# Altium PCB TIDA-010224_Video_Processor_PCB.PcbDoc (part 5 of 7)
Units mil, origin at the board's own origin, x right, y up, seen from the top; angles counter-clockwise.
Board outline 2355.46 x 4164 mil, 10 copper layers (L1-Top Layer, L2-GND, L3-SIG1, L4-GND, L5-PWR, L6-PWR, L7-GND, L8-SIG2, L9-GND, L10-Bottom Layer), stack 62.2 mil thick; 508 components, 274 nets, 3619 pads, 705 vias.
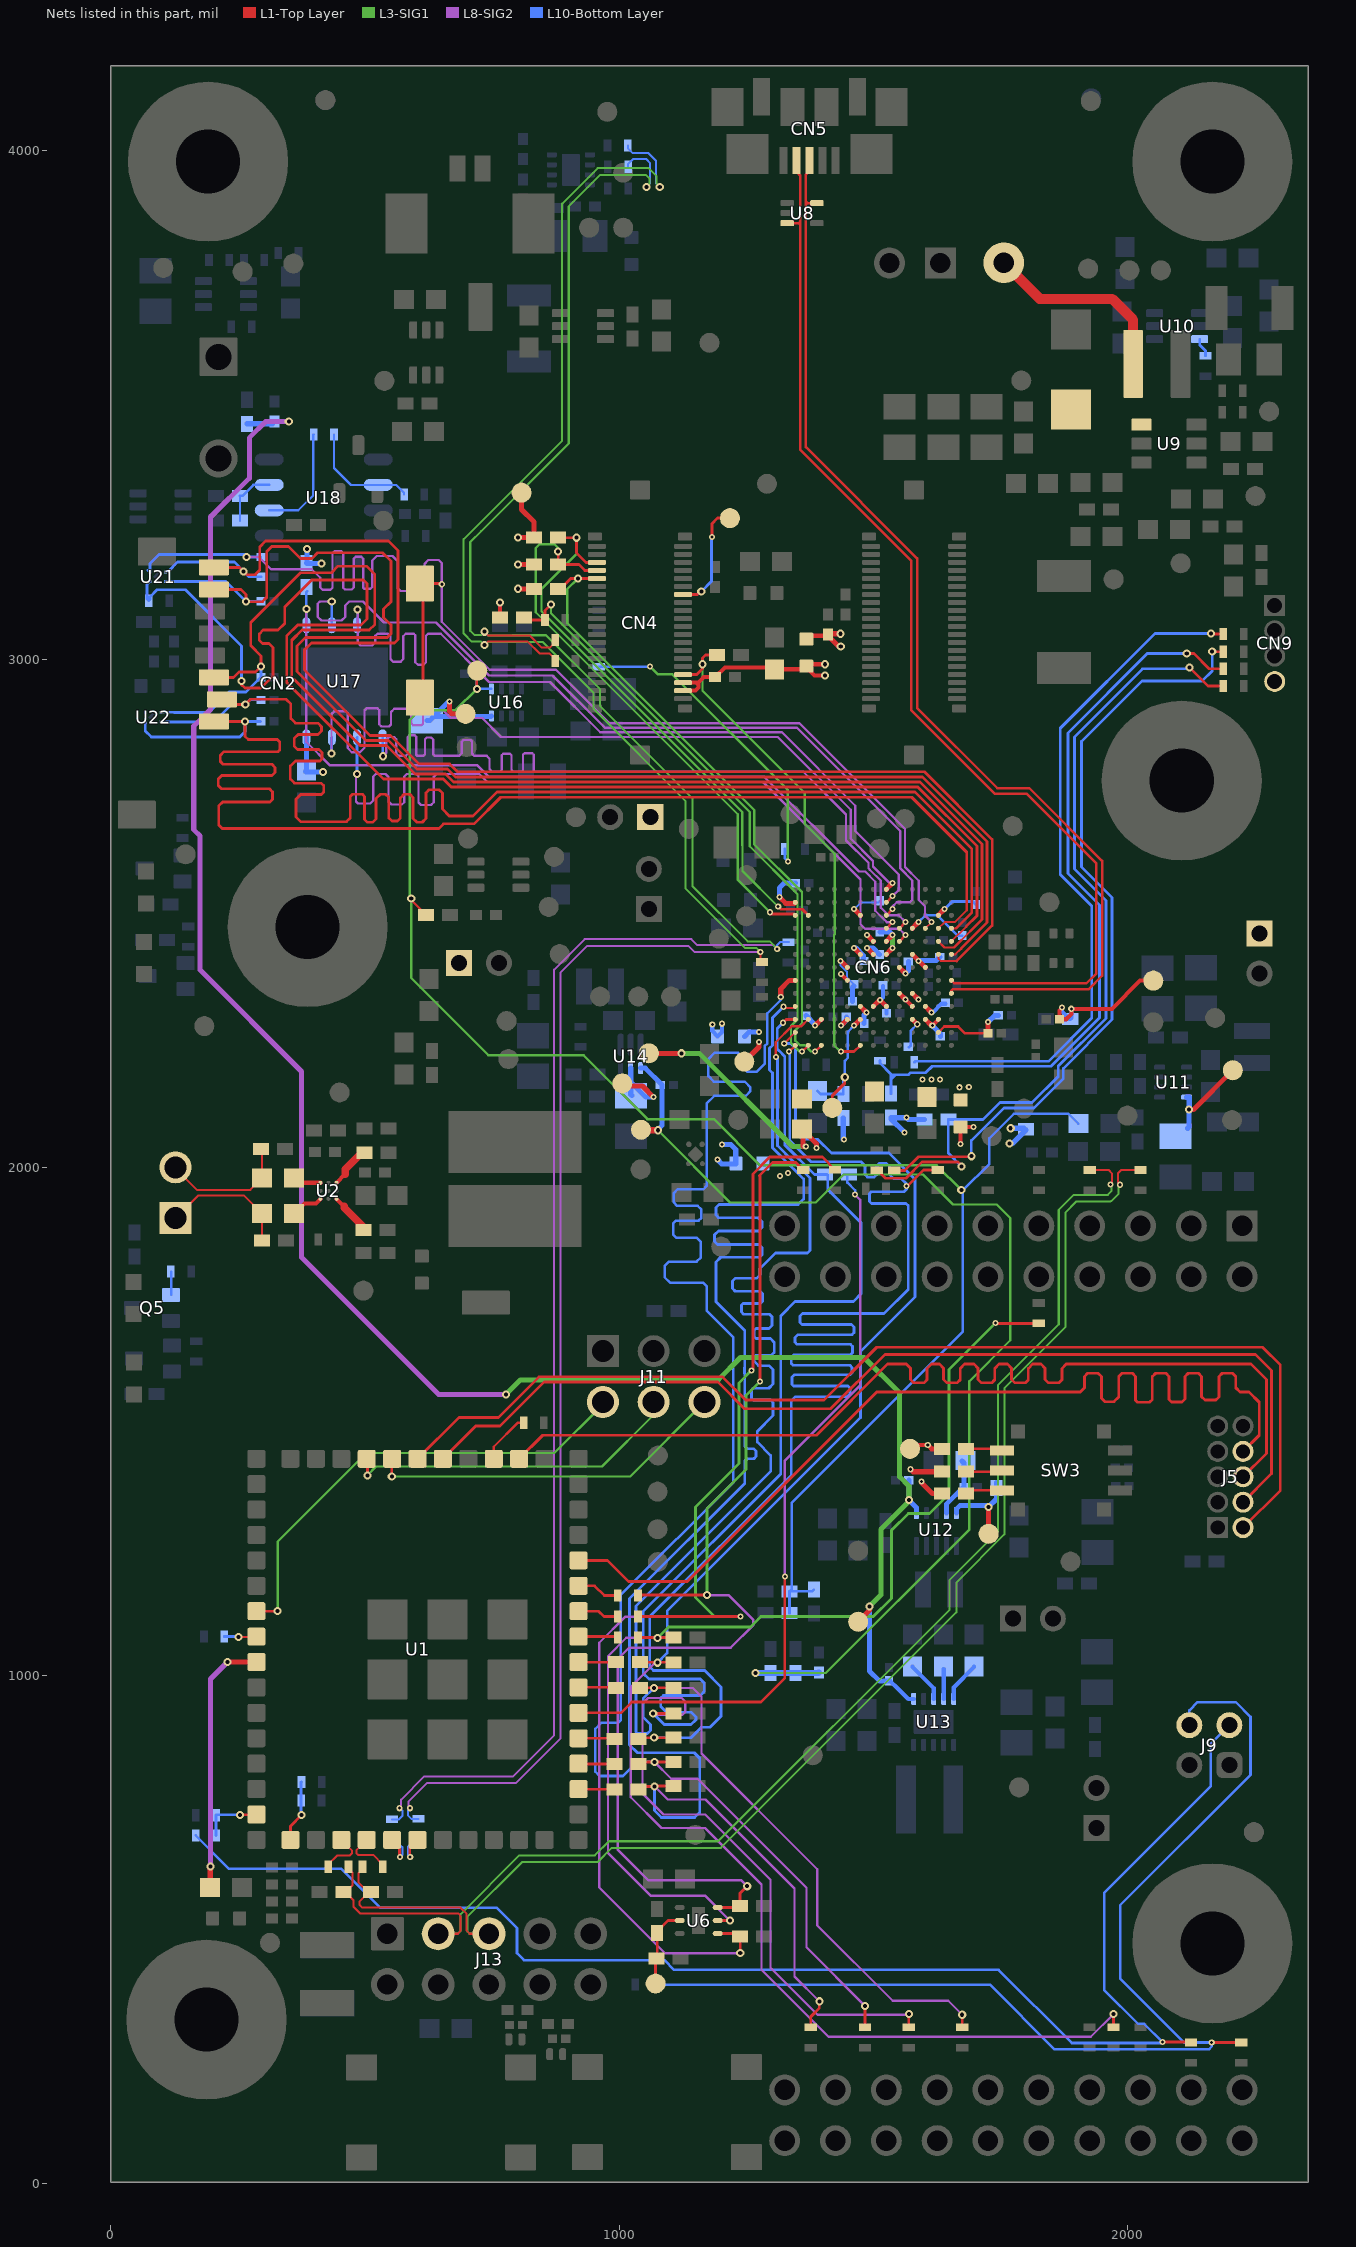
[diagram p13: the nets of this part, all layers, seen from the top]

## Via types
v1: diameter 16, hole 8, L1-Top Layer to L10-Bottom Layer, tented both sides, 414 vias
v2: diameter 12, hole 6, L1-Top Layer to L10-Bottom Layer, tented both sides, 243 vias
v3: diameter 19.68, hole 7.87, L1-Top Layer to L10-Bottom Layer, 44 vias
v4: diameter 14, hole 6, L1-Top Layer to L10-Bottom Layer, tented both sides, 2 vias
v5: diameter 16, hole 8, L1-Top Layer to L10-Bottom Layer, tented top, 1 vias
v6: diameter 20, hole 10, L1-Top Layer to L10-Bottom Layer, tented both sides, 1 vias

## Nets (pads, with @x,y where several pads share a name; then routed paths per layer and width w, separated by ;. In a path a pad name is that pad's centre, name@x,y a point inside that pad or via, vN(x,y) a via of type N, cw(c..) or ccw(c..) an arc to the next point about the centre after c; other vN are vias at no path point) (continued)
NetQ5_1: Q5.1 R180.2 | length 46.3
  L10-Bottom Layer w4.5: R180.2@118,1795 118.4,1794.6 Q5.1@118.4,1748.89
NetR1_2: R1.2 U1.36 | length 514.8
  L1-Top Layer w10: R1.2@195.35,582.95 195.35,623.64 v1(196,624.29) ; v1(229.33,1026.67) U1.36@286.33,1026.67
  L8-SIG2 w10: v1(196,624.29) 196,993.33 v1(229.33,1026.67)
NetR2_1: R2.1 U2.C3 | length 58.9
  L1-Top Layer w8: R2.1@360.5,1979 360.5,1981.28 372.1,1969.68 U2.C3@412.32,1969.68
NetR3_1: R3.1 U2.A3 | length 63.9
  L1-Top Layer w8: R3.1@360.5,1909 380.5,1929 403.14,1929 U2.A3@412.32,1938.18
NetR8_1: R8.1 U1.46 | length 95.5
  L1-Top Layer w4: R8.1@427.48,623.74 427.48,628.45 445.03,646 470.1,646 474,649.9 474,655.96 U1.46@453.26,676.7
NetR9_2: R9.2 U2.A1 | length 83.4
  L1-Top Layer w8: U2.A1@443.82,1938.18 459,1923
  L1-Top Layer w15: 459,1923 459,1920.9 497.38,1882.53 R9.2@497.38,1877
NetR10_2: R10.2 U2.C1 | length 82.8
  L1-Top Layer w8: U2.C1@443.82,1969.68 461,1986.86
  L1-Top Layer w15: 461,1986.86 461,1996.28 489.63,2024.91 R10.2@498.26,2024.91
NetR12_1: R12.1 U1.47 | length 100.3
  L1-Top Layer w4: U1.47@503.26,676.7 482.92,656.36 482.92,650.38 486.12,647.17 515.74,647.17 534.89,628.03 R12.1@534.89,623.74
NetR17_1: R17.1 U1.19 | length 102
  L1-Top Layer w5: U1.19@753.26,1426.63 753.26,1450.26 800.61,1497.61 R17.1@812,1497.61
NetR25_1: R25.1 U1.4 | length 74.1
  L1-Top Layer w5: U1.4@920.19,826.67 920.85,826 R25.1@990.38,826 R25.1@994,826
NetR26_1: R26.1 U1.3 | length 74.1
  L1-Top Layer w5: U1.3@920.19,776.67 993.33,776.67 R26.1@994,776
NetR27_1: R27.1 U1.8 | length 76.9
  L1-Top Layer w5: U1.8@920.19,1026.67 996.67,1026.67 R27.1@997,1026.34
NetR28_1: R28.1 U1.7 | length 77.1
  L1-Top Layer w5: U1.7@920.19,976.67 996.2,976.67 R28.1@997,975.87
NetR29_1: R29.1 U1.5 | length 77.5
  L1-Top Layer w5: U1.5@920.19,876.67 995.27,876.67 R29.1@997,874.93
NetR30_1: R30.1 U1.11 | length 83.1
  L1-Top Layer w5: U1.11@920.19,1176.67 951.79,1176.67 970.9,1157.56 R30.1@995.35,1157.56
NetR31_1: R31.1 U1.10 | length 81.2
  L1-Top Layer w5.5: U1.10@920.19,1126.67 959.33,1126.67 970,1116 R31.1@997,1116
NetR32_1: R32.1 U1.9 | length 77.5
  L1-Top Layer w5.5: U1.9@920.19,1076.67 995.33,1076.67 R32.1@997,1075
NetR55_1: R55.1 SW3.1 | length 72
  L1-Top Layer w5: R55.1@1682.73,1446.12 1750.69,1446.12 SW3.1@1753.55,1443.26
NetR56_1: R56.1 SW3.3 | length 73.5
  L1-Top Layer w5.5: R56.1@1682.73,1358.12 1689.13,1364.52 SW3.3@1753.55,1364.52
NetR57_1: R57.1 SW3.2 | length 71.8
  L1-Top Layer w5: R57.1@1682.92,1401.12 1750.77,1401.12 SW3.2@1753.55,1403.89
NetR90_2: R90.2 U10.3 | length 37.4
  L10-Bottom Layer w5.5: U10.3@2142.29,3629.58 2142.29,3618.63 2154,3606.92 R90.2@2154,3597
NetR108_2: R108.2 U13.5 | length 80.2
  L10-Bottom Layer w8: U13.5@1658.37,954.15 1658.37,976.87 1698.66,1017.16 R108.2@1698.66,1017.63
NetR109_1: R109.1 R110.2 U12.4 | length 118.9
  L10-Bottom Layer w10: U12.4@1643.86,1319.65 1643.86,1337.04 1677.57,1370.75 R109.1@1678.53,1370.75 1678.53,1418.15 R110.2@1674.69,1422
NetR112_2: R112.2 U13.4 | length 59.3
  L10-Bottom Layer w8: R112.2@1638.37,1013.34 1638.68,1013.03 U13.4@1638.68,954.15
NetR114_2: R114.2 U13.3 | length 80.7
  L10-Bottom Layer w8: R114.2@1577.54,1017.63 1577.54,1017.13 1619,975.67 U13.3@1619,954.15
NetR121_1: R121.1 U1.6 | length 1499.7
  L1-Top Layer w5: U1.6@920.19,926.67 1003.67,926.67 1025,948 1279,948 1326,995 v2(1326,1195)
  L8-SIG2 w5: v2(1326,1195) 1326,1422.9 1474,1570.9 1474,1936.29 v2@1461.5,1948.79
  L10-Bottom Layer w5: R121.1@1449.13,1986 1449.13,1970.24 1464.42,1954.95 v2(1464.42,1947)
NetR154_1: R154.1 R158.2 U18.6 | length 227.3
  L10-Bottom Layer w4.5: R158.2@439,3442 439.03,3376.18 472.32,3342.89 U18.6@526.01,3342.89 561.53,3342.89 576.81,3327.6 R154.1@576.81,3324.01
NetR155_1: R155.1 U1.49 | length 87.8
  L1-Top Layer w5.5: v2@587.86,642.63 587.86,661.3 U1.49@603.26,676.7
  L10-Bottom Layer w4: v2(588.86,643) 584.75,647.11 584.75,663.87 595.69,674.82 R155.1@605,674.82
NetR156_1: R156.1 U1.48 | length 86.5
  L1-Top Layer w5.5: U1.48@553.26,676.7 568,661.96 v2@568,643.2
  L10-Bottom Layer w4: R156.1@553,675.54 560.11,675.54 573.25,662.41 573.25,647.25 v2(569,643)
NetR158_1: R158.1 U18.2 | length 218.8
  L10-Bottom Layer w4.5: U18.2@311.44,3292.89 368.49,3292.89 398.32,3322.72 398.32,3441.32 R158.1@399,3442
NetR159_1: R159.1 R160.1 U1.44 | length 123.6
  L1-Top Layer w5.5: U1.44@353.26,676.7 353.26,703.5 v1(375.09,725.33)
  L10-Bottom Layer w5.5: R159.1@374.86,790.65 374.22,790.01 R160.1@374.22,754 374.22,727.74 375.09,726.87 v1(375.09,725.33)
NetR172_2: R172.2 R173.2 U18.3 | length 115.5
  L10-Bottom Layer w4.5: R173.2@253.81,3272.35 R172.2@253.81,3321.35
  L10-Bottom Layer w5: R172.2@253.81,3321.35 258.55,3321.35 280.09,3342.89 U18.3@311.44,3342.89
NetR175_2: R175.2 U1.35 | length 63.6
  L1-Top Layer w4: v1(251.28,1076.2) 285.87,1076.2 U1.35@286.33,1076.67
  L10-Bottom Layer w5.5: R175.2@223.09,1076.67 250.81,1076.67 v1(251.28,1076.2)
NetR176_1: R176.1 R177.1 U1.42 | length 119.9
  L1-Top Layer w5.5: v1(254.22,726) 285.67,726 U1.42@286.33,726.67
  L10-Bottom Layer w5.5: R177.1@206.92,685.43 R176.1@206.92,725.33 207.59,726 v1(254.22,726)
OPT_ADDR: ID.1 R33.2 R34.1 U6.2 | length 157.3
  L1-Top Layer w5.5: ID.1@1071.7,394.05 1071.7,441.73 R33.2@1073.33,443.36 1074.95,444.98 R34.1@1074.95,493.82 1074.95,496.95 1096.15,518.15 U6.2@1119.17,518.15
OPT_INT: R32.2 R65.2 R187.1 U6.5 | length 2117.9
  L1-Top Layer w5.5: R32.2@1037,1075 R187.1@1107.38,1075 R187.1@1107.48,1075 ; U6.5@1193.97,518.15 v1(1217.78,518.15) ; v2(1740.75,1693.79) 1744.54,1693.79 1745.33,1693 R65.2@1825.78,1693
  L3-SIG1 w5.5: v1(1075.48,1074.27) 1096.98,1095.77 1258.55,1095.77 1278.78,1116 1500,1116 1536,1152 1536,1285.98 1569.02,1319 1610.53,1319 1649.01,1357.48 1649.01,1602.05 v2(1740.75,1693.79)
  L8-SIG2 w4.5: v1(1075.48,1074.27) 1014.05,1074.27 978,1038.22 978,650.64 1061.64,567 1168.93,567 v1(1217.78,518.15)
OPT_SCL: R31.2 R44.2 R49.1 U6.4 | length 2563.7
  L1-Top Layer w5.5: R31.2@1037,1116 v2(1239,1116) ; U6.4@1193.97,492.56 1232.31,492.56 R44.2@1238.22,486.65 v1(1238.22,453.81) ; v2(1260.44,1600.68) 1263.16,1603.4 1263.16,1987.07 1296.32,2020.23 1399.77,2020.23 R49.1@1425,1995
  L3-SIG1 w5.5: v2(1239,1116) 1187.84,1116 1150.2,1153.64 1150.2,1331.93 1235.73,1417.47 1235.73,1575.97 v2(1260.44,1600.68)
  L8-SIG2 w4.5: v1(1238.22,453.81) 1090.19,453.81 961,583 961,1064.39 1012.61,1116 v2(1239,1116)
OPT_SDA: R30.2 R43.2 R47.1 U6.6 | length 2272.2
  L1-Top Layer w5.5: R30.2@1038.63,1158.33 v1(1173,1158.33) ; U6.6@1193.97,543.74 1235.59,543.74 R43.2@1238,546.15 1238,571.59 v1(1251.97,585.56) ; v2(1277,1579) 1277,1982.68 1276,1983.68 1302,2009.68 1347.57,2009.68 R47.1@1362.42,1994.84
  L3-SIG1 w5.5: v1(1173,1158.33) 1173,1329 1249.41,1405.41 1249.41,1551.41 v2(1277,1579)
  L8-SIG2 w4.5: v1(1173,1158.33) 1215.23,1158.33 1264.13,1109.43 1264.13,1099.49 1219.65,1055 1020,1055 997,1032 997,658 1058,597 1240.53,597 v1(1251.97,585.56)
OV_RST#: C102.1 CN6.C8 R122.1 RST.1 | length 281.9
  L1-Top Layer w5.5: RST.1@1419.35,2117 1419.35,2140.88 1444,2165.54 v1(1444,2177.37)
  L1-Top Layer w10: v2(1462.36,2279) CN6.C8@1474.59,2291.23
  L10-Bottom Layer w5: 1444,2209.47 1449.86,2215.33 1449.86,2266.5 v2(1462.36,2279)
  L10-Bottom Layer w5.5: C102.1@1390.52,2150.06 1396.13,2144.45 R122.1@1441,2144.45 v1@1441,2176.46 ; v1(1444,2177.37) 1444,2209.47
OV_RXD0: R52.2 R83.2 R111.1 | length 1638.2
  L1-Top Layer w5.5: R52.2@1507,1994 1508.83,1994 1524.36,1978.47 1564.23,1978.47 1596.05,2010.29 1667,2010.29 v1@1672,2005.29 ; v1(2122.13,2983.54) 2158.7,2946.98 R83.2@2188.81,2946.98
  L10-Bottom Layer w5.5: v1(1673.76,2001.79) 1647.62,2027.92 R111.1@1647.62,2094 1716.22,2094 1749.76,2127.54 1812.4,2127.54 1864,2179.14 1864,2199.24 1957.78,2293.02 1957.78,2525.22 1896,2587 1896,2847 2029.98,2980.98 2119.57,2980.98 v1(2122.13,2983.54)
OV_RXD1: R82.2 R117.1 R119.2 | length 1513.1
  L1-Top Layer w5.5: v1(2116.82,3011.12) 2130.92,3011.12 2161.06,2980.98 R82.2@2188.81,2980.98
  L10-Bottom Layer w5.5: R119.2@1513,2210 1513,2205.22 1535,2183.22 ; R117.1@1535,2144.92 1535,2173.25 ; v1(2116.82,3011.12) 2039.12,3011.12 1882.93,2854.93 1882.93,2589.79 1883,2589.72 1883,2578.01 1945,2516.01 1945,2294.4 1849.6,2199 1616,2199 1603.32,2186.32 1573.46,2186.32 1569.38,2182.25 1544,2182.25 ; 1535,2173.25 1544,2182.25 ; 1535,2173.25 1535,2183.22 ; 1535,2183.22 1535.97,2182.25 1544,2182.25
OV_TXD0: R53.2 R81.2 | length 1536.1
  L1-Top Layer w5.5: R53.2@1541.34,1994 1561.82,1994 1588.82,2021 v1@1692,2021 ; v1(2166.96,3015) 2162.53,3015 2162.17,3014.64 R81.2@2188.81,3014.64
  L10-Bottom Layer w5.5: v1(1693,2022) 1693,2052.7 1757.3,2117 1816,2117 1874,2175 1874,2194.72 1970,2290.72 1970,2531 1910,2591 1910,2838.33 2028.67,2957 2146.93,2957 2166.96,2977.03 v1(2166.96,3015)
OV_TXD1: R80.2 R115.2 | length 1379.6
  L1-Top Layer w5.5: v1(2164.68,3050.75) 2165.7,3049.72 R80.2@2188.81,3049.72
  L10-Bottom Layer w5.5: R115.2@1581,2207 1583,2209 1845.46,2209 1930,2293.54 1930,2514.5 1868,2576.5 1868,2864 2054.75,3050.75 v1(2164.68,3050.75)
P16_JTAG_TDI: J5.8 U1.12 | length 2071.4
  L1-Top Layer w5.5: U1.12@920.19,1226.67 976.84,1226.67 1018.5,1185 1134,1185 1166,1217 1506.83,1557.83 1907.33,1557.83 1915.84,1566.34 1915.84,1588.78 1921.89,1594.83 1942.2,1594.83 1948.83,1588.2 1948.83,1545.71 1955.54,1539 1973.68,1539 1983.17,1548.49 1983.17,1588.2 1989.8,1594.83 2010.11,1594.83 2016.16,1588.78 2016.16,1541.84 2020.27,1537.73 2043.73,1537.73 2049.17,1543.17 2049.17,1588.2 2055.8,1594.83 2076.11,1594.83 2082.16,1588.78 2082.16,1543.37 2086.99,1538.54 2107.57,1538.54 2113.17,1544.14 2113.17,1588.2 2119.8,1594.83 2140.11,1594.83 2146.16,1588.78 2146.16,1548.6 2152.76,1542 2173.81,1542 2180.17,1548.36 2180.17,1588.2 2186.8,1594.83 2207.11,1594.83 2213.16,1588.78 2213.16,1566.34 2221.67,1557.83 2239.45,1557.83 2259.55,1537.73 2259.55,1472.98 J5.8@2227.7,1441.13
P17_JTAG_TDO: J5.6 U1.18 | length 2054.9
  L1-Top Layer w5.5: U1.18@803.26,1426.63 849.63,1473 1388.34,1473 1528.34,1613 1564.84,1613 1573.01,1604.83 1573.01,1582.63 1579.64,1576 1599.95,1576 1606,1582.05 1606,1604.49 1614.51,1613 1630,1613 1638.17,1604.83 1638.17,1582.63 1644.8,1576 1665.11,1576 1671.16,1582.05 1671.16,1604.49 1679.67,1613 1698,1613 1706.17,1604.83 1706.17,1582.63 1712.8,1576 1733.11,1576 1739.16,1582.05 1739.16,1604.49 1747.67,1613 1764,1613 1772.17,1604.83 1772.17,1582.63 1778.8,1576 1799.11,1576 1805.16,1582.05 1805.16,1604.49 1813.67,1613 1830,1613 1838.17,1604.83 1838.17,1582.63 1844.8,1576 1865.11,1576 1871.16,1582.05 1871.16,1604.49 1879.67,1613 2243.28,1613 2273.87,1582.41 2273.87,1437.3 J5.6@2227.7,1391.13
P19_JTAG_TCK: J5.4 U1.21 | length 2054.8
  L1-Top Layer w5.5: U1.21@653.26,1426.63 717.77,1491.13 765.2,1491.13 851.87,1577.8 1194.2,1577.8 1247,1525 1416,1525 1523,1632 2251.87,1632 2283.87,1600 2283.87,1397.3 J5.4@2227.7,1341.13
P20_JTAG_TMS: J5.2 U1.22 | length 2191.3
  L1-Top Layer w5.5: U1.22@603.26,1426.63 684.63,1508 762.42,1508 842.21,1587.8 1203.33,1587.8 1249.13,1542 1402.89,1542 1506.89,1646 2266,1646 2301,1611 2301,1364.43 J5.2@2227.7,1291.13
PG_1V1: PG_1.1V.1 R137.1 U14.2 | length 185.2
  L1-Top Layer w10: PG_1.1V.1@1006.23,2165.13 1011.27,2160.09 1045.89,2160.09 v2(1067.79,2138.19)
  L10-Bottom Layer w10: U14.2@1022.79,2195.21 1022.79,2167.96 ; R137.1@1025,2141 1022.79,2143.21 1022.79,2167.96 ; v2(1067.79,2138.19) 1052.57,2138.19 1022.79,2167.96
PG_1V8: PG_1.8V.1 R152.1 U16.8 | length 226.1
  L1-Top Layer w10: v2(666,2916.5) 666,2897.57 671.25,2892.32 PG_1.8V.1@697.73,2892.32
  L10-Bottom Layer w10: R152.1@622,2879 627.44,2879 R152.1@635.44,2887 ; v2(666,2916.5) 664.94,2916.5 R152.1@635.44,2887 ; U16.8@748.67,2888.2 747.47,2887 R152.1@635.44,2887
PG_1V35: PG_1.35V.1 R91.1 U11.8 | length 180.3
  L1-Top Layer w10: v1(2121.03,2114) 2130.44,2114 PG_1.35V.1@2207.53,2191.09
  L10-Bottom Layer w10: U11.8@2116.83,2137.98 2121.8,2137.98 v1@2121.8,2118.97 ; R91.1@2118.8,2077.03 2121.03,2079.27 v1(2121.03,2114)
PG_3V3A: PG_3.3V.1 R107.1 U12.5 | length 182.7
  L1-Top Layer w10: PG_3.3V.1@1727,1279 v1(1727,1332)
  L10-Bottom Layer w10: U12.5@1663.54,1319.65 1663.54,1327.4 1671.14,1335 1724,1335 v1(1727,1332) 1742.54,1347.54 R107.1@1742.54,1369.06 R107.1@1742.54,1379.69
PIR_OUT1: J9.4 R84.1 R136.2 | length 2237.1
  L1-Top Layer w5: v2(2166,278) R84.1@2224.03,278
  L10-Bottom Layer w5: R136.2@1071.7,392 1729.48,392 1856.85,264.63 2160.24,264.63 2166,270.38 v2(2166,278) 2111.42,278 1985.7,403.72 1985.7,548.07 2242.29,804.66 2242.29,918.82 2213.25,947.87 2138.38,947.87 2121.91,931.4 J9.4@2121.91,902.37
PIR_OUT2: J9.2 R75.1 R177.2 | length 2937.9
  L1-Top Layer w5: v2(2068.76,279) 2122.1,279 2123.05,279.95 R75.1@2125,278
  L10-Bottom Layer w5: R177.2@166.92,685.43 232.57,619.78 453.26,619.78 529.54,543.5 758.5,543.5 799,503 799,453.71 812.71,440 1089,440 1108,421 1746.8,421 1890.8,277 2066.76,277 v2(2068.76,279) 2032.82,314.94 2021,314.94 1954.32,381.62 1954.32,572.23 2164,781.91 2164,865.72 J9.2@2200.65,902.37
PWR_EN: C130.2 PWR_EN.1 R116.1 R118.1 R170.1 U12.1 U13.1 | length 4076
  L1-Top Layer w10: PWR_EN.1@1470.37,1105.91 1492.84,1128.38 v1(1492.84,1136.22)
  L3-SIG1 w10: v1(777,1553) 806,1582 1195,1582 1239,1626 1482,1626 1552,1556 1552,1391 1570,1373 v1(1570,1345.36) 1570,1342.56 1515,1287.57 1515,1158.38 v1(1492.84,1136.22)
  L8-SIG2 w10: v1(350,3467.63) 304.49,3467.63 272.39,3435.53 272.39,3356.01 196,3279.61 196,2901 163,2868 163,2664.57 175.5,2652.07 175.5,2388.31 375,2188.81 375,1822.98 644.98,1553 v1(777,1553)
  L10-Bottom Layer w8: R118.1@1533.35,989.63 1547.92,975.07 1568.84,954.15 U13.1@1579.63,954.15
  L10-Bottom Layer w10: R170.1@267.38,3463.19 317.56,3463.19 C130.2@322,3467.63 v1(350,3467.63) ; v1(1492.84,1136.22) 1492.84,1008.73 1511.94,989.63 R118.1@1533.35,989.63 ; R116.1@1570,1384.69 v1(1570,1345.36) 1584.8,1330.56 U12.1@1584.8,1319.65
RDY: CN6.F13 R25.2 R39.2 R50.2 | length 3300.1
  L1-Top Layer w5.5: R25.2@1034,826 1038,830 v1(1069.58,830) R39.2@1107.38,830 ; R50.2@1483.78,311.81 1484,312.03 v1(1484,350)
  L1-Top Layer w10: v2(1318,2335) 1318,2351.09 1334.91,2368 CN6.F13@1346.64,2368
  L8-SIG2 w4.5: v1(1069.58,830) 1102.58,797 1154,797 1368.56,582.44 1368.56,465.44 v1(1484,350)
  L10-Bottom Layer w5: v1(1069.58,830) 1034.78,830 1007.21,802.43 961.57,802.43 953,811 953,894.95 965.4,907.34 998.31,907.34 1002.96,912 1002.96,1158.33 1224.69,1380.06 1224.69,1665.53 1172.25,1717.97 1172.25,1766.27 1165.77,1772.75 1100.68,1772.75 1089.61,1783.82 1089.61,1805.61 1098.37,1814.36 1152.31,1814.36 1160.86,1822.91 1160.86,1853.45 1152.96,1861.35 1113.17,1861.35 1106.31,1868.2 1106.31,1889.15 1112.28,1895.12 1156.39,1895.12 1161.68,1900.4 1161.68,1917.43 1154.69,1924.41 1114.15,1924.41 1107.51,1931.06 1107.51,1949.45 1115,1956.95 1165.59,1956.95 1172.25,1963.6 1172.25,2125.7 1187.47,2140.92 1249.41,2140.92 1258.41,2149.92 1258.41,2157.29 1247.23,2168.47 1186.47,2168.47 1175.46,2179.49 1175.46,2213.12 1187.84,2225.5 1234.22,2225.5 1240.16,2219.56 1240.16,2200.09 1251.79,2188.46 1270.88,2188.46 1286.16,2203.74 1286.16,2238.53 1291.77,2244.15 1291.77,2303.29 1318,2329.52 v2(1318,2335)
SC_CD: CN2.10 CN6.K3 R167.1 U21.4 | length 2797.2
  L1-Top Layer w4: CN6.K3@1602.54,2470.36 v2(1614.77,2482.59)
  L1-Top Layer w5.5: CN2.10@608.03,2924.29 614.01,2930.26 614.01,3124.66 608.03,3130.64 CN2.10@608.03,3148.7 649.71,3148.7 v2(651,3147.41)
  L8-SIG2 w4.5: v1(267,3201) 291,3201 315,3177 395,3177 412,3160 412,3141.2 416.51,3136.69 432.01,3136.69 436,3140.68 436,3208 441,3213 452.58,3213 457.22,3208.36 457.22,3140.29 460.51,3137 473.8,3137 478,3141.2 478,3198 481.51,3201.51 492.49,3201.51 496.3,3197.7 496.3,3140.7 498.49,3138.51 510.51,3138.51 514,3142 514,3194 523,3203 554,3203 564,3193 564,3140 570,3134 613.31,3134 616.81,3137.51 616.81,3187.41 624.4,3195 645,3195 651,3189 v2(651,3147.41) 651,3073.54 745.22,2979.31 875.85,2979.31 981.16,2874 1354.83,2874 1562.39,2666.44 1562.39,2591.12 1589.54,2563.97 1589.54,2526.34 1601.93,2513.96 1601.93,2495.43 v2(1614.77,2482.59)
  L10-Bottom Layer w5.5: 73.1,3175 U21.4@76.65,3171.45 76.65,3188.08 94.36,3205.8 262.2,3205.8 v1(267,3201) R167.1@294.36,3201
SC_CLK: CN6.J1 R184.2 U21.3 | length 2842.4
  L1-Top Layer w4: CN6.J1@1653.72,2444.77 1682.81,2473.86
  L1-Top Layer w5.5: v1(257,2957.18) 257,2949.63 263.65,2942.98 295.44,2942.98 319,2966.54 319,3023 311,3031 298,3031 292,3037 292,3049.72 299.4,3057.12 328.81,3057.12 342,3070.31 342,3102.98 395.02,3156 496.76,3156 504,3148.76 504,3078.91 492.21,3067.12 367.56,3067.12 345.77,3045.33 345.77,2954.57 536.34,2764 654,2764 669.64,2748.36 1587.62,2748.36 1704,2631.99 1704,2495.05 1682.81,2473.86
  L10-Bottom Layer w5.5: R184.2@74.52,3115 71,3118.52 71,3146.91 U21.3@76.65,3152.55 ; R184.2@76.65,3117.12 76.65,3122.63 90.52,3136.5 146.5,3136.5 257,3026 v1(257,2957.18)
SC_CMD: CN2.3 CN6.J2 R164.1 U22.1 | length 2843.5
  L1-Top Layer w4: CN6.J2@1628.13,2444.77 1640.25,2432.65 1658.85,2432.65 1691,2464.8
  L1-Top Layer w5.5: CN2.3@202.52,2964.05 240.8,2964.05 251.75,2975 284.31,2975 v1(295.02,2985.71) 295.02,3006.5 275,3026.52 275,3072.35 372.65,3170 434,3170 447,3183 502.71,3183 519.27,3166.44 519.27,3068.27 508.12,3057.12 375.79,3057.12 355.77,3037.11 355.77,2964.82 490.59,2830 542.06,2830 598.06,2774 658.14,2774 673.78,2758.36 1591.77,2758.36 1714,2636.13 1714,2487.8 1691,2464.8
  L10-Bottom Layer w5.5: U22.1@98.23,2895.44 124,2895.44 124.44,2895 192.53,2895 232.78,2935.25 265.56,2935.25 R164.1@295.02,2964.71 v1(295.02,2985.71)
SC_D0: CN2.7 CN6.H1 R163.1 U21.2 | length 2842
  L1-Top Layer w4: CN6.H1@1653.72,2419.18 1661.48,2419.18 1673.01,2430.71
  L1-Top Layer w5.5: CN2.7@202.52,3137.28 255.64,3137.28 266,3126.91 v1(266,3113.16) 298.06,3113.16 306.69,3121.78 306.69,3211.9 316.37,3221.58 349.48,3221.58 373.06,3198 395.31,3198 406.74,3209.43 534.57,3209.43 550.94,3193.06 550.94,3112.94 536.34,3098.34 536.34,3082.18 550.94,3067.58 550.94,3049.93 543.76,3042.76 382.61,3042.76 366,3026.14 366,2976 502,2840 546.2,2840 602.2,2784 662.28,2784 677.92,2768.36 1596.64,2768.36 1724,2641 1724,2481.7 1673.01,2430.71
  L10-Bottom Layer w5.5: U21.2@107.35,3152.55 226.61,3152.55 v1(266,3113.16) 266.55,3113.71 R163.1@295.02,3113.71
SC_D1: CN2.8 CN6.H2 R168.1 U21.1 | length 2843.8
  L1-Top Layer w4: CN6.H2@1628.13,2419.18 1628.13,2410.61 1632.56,2406.19 1664.16,2406.19
  L1-Top Layer w5.5: CN2.8@202.52,3180.59 253.2,3180.59 v1(261.19,3172.6) 267.79,3166 283.25,3166 292.93,3175.68 292.93,3221 304.3,3232.38 546.18,3232.38 564.69,3213.86 564.69,3038.83 557.66,3031.8 394.36,3031.8 381.08,3018.53 381.08,2978.53 509.62,2850 550.34,2850 606.34,2794 666.43,2794 682.06,2778.36 1600.78,2778.36 1734,2645.14 1734,2476.03 1676.72,2418.75 1664.16,2406.19
  L10-Bottom Layer w5.5: 113,3173 131,3191 242.79,3191 v1(261.19,3172.6) 271.79,3162 R168.1@295.01,3162
SC_D2: CN2.1 CN6.K2 R166.1 U22.3 | length 2844.6
  L1-Top Layer w4: CN6.K2@1628.13,2470.36 1640.36,2482.59 1660.51,2482.59 1684,2506.08
  L1-Top Layer w5.5: CN2.1@202.52,2877.44 v1(264.05,2877.44) 264.05,2848 270.36,2841.69 327.31,2841.69 332.13,2836.87 332.13,2821.54 328.58,2818 222.27,2818 215,2810.73 215,2799 220.85,2793.15 316.85,2793.15 323.07,2786.93 323.07,2777.07 317,2771 218,2771 211.23,2764.23 211.23,2751.44 217.68,2745 312,2745 318.09,2738.91 318.09,2724.34 312.62,2718.86 219.92,2718.86 212,2710.94 212,2674.06 219.06,2667 645.57,2667 654.56,2675.99 714.71,2675.99 767.01,2728.29 1575.83,2728.29 1684,2620.13 1684,2506.08
  L10-Bottom Layer w5.5: U22.3@67.52,2876.54 67.52,2858.55 79.5,2846.57 253.51,2846.57 264.05,2857.11 v1(264.05,2877.44) R166.1@294.36,2877.44
SC_D3: CN2.2 CN6.K1 R165.1 U22.2 | length 2840.2
  L1-Top Layer w4: CN6.K1@1653.72,2470.36 1662.69,2470.36
  L1-Top Layer w5.5: CN2.2@218.27,2920.74 228.01,2911 v1(264.38,2911) 274.38,2921 344.48,2921 354,2911.48 354,2882.86 362.85,2874.01 407.27,2874.01 414.26,2867.02 414.26,2858.61 407.52,2851.86 368.58,2851.86 361.31,2844.6 ; 360.89,2844.17 360.89,2828.43 367.3,2822.01 409.42,2822.01 415.19,2816.24 415.19,2803.94 411.1,2799.86 363.25,2799.86 353,2789.61 353,2764.4 361.39,2756.01 413.67,2756.01 418.55,2751.14 418.55,2738.15 414.26,2733.86 373.44,2733.86 364.02,2724.45 364.02,2689.55 373.33,2680.25 463.79,2680.25 471,2687.46 471,2729.62 475.61,2734.23 494.85,2734.23 499.14,2729.95 499.14,2684.26 504.52,2678.88 514.81,2678.88 521.6,2685.67 521.6,2725.66 530.17,2734.23 540.33,2734.23 546.81,2727.76 546.81,2687.39 552.93,2681.28 563.5,2681.28 569.46,2687.25 569.46,2726.94 576.76,2734.23 587.86,2734.23 594.33,2727.76 594.33,2686.59 601.93,2679 612.57,2679 620,2686.43 620,2737 626,2743 645.85,2743 652.14,2736.71 652.14,2704.92 665.65,2691.41 712.66,2691.41 759.62,2738.36 1582.32,2738.36 1694,2626.68 1694,2501.67 1662.69,2470.36
  L10-Bottom Layer w5.5: U22.2@98.23,2876.54 203.13,2876.54 237.59,2911 v1(264.38,2911) 274.12,2920.74 R165.1@295.02,2920.74
SFC_CLK: CN6.J5 U17.6 | length 1681
  L1-Top Layer w5.5: CN6.J5@1551.36,2444.77 v2(1563.59,2457)
  L8-SIG2 w4.5: v1(484,2774) 482,2774 482,2720.06 486.06,2716 510.21,2716 516,2721.79 516,2769 521,2774 540,2774 546,2768 546,2720 552,2714 572.36,2714 577,2718.64 577,2769 582,2774 601,2774 605,2770 605,2717.96 609.96,2713 629.77,2713 635.36,2718.59 635.36,2768.36 641,2774 724.87,2774 740.51,2758.36 1282.86,2758.36 1475,2566.22 1475,2478.22 1483.93,2469.29 1551.3,2469.29 v2(1563.59,2457)
  L10-Bottom Layer w5.5: v1(484,2774) 484,2845.68 U17.6@484.52,2846.2
SFC_MOSI0: CN6.K5 U17.5 | length 1681.4
  L1-Top Layer w5.5: CN6.K5@1551.36,2470.36 v2(1563.59,2482.59)
  L8-SIG2 w4.5: v1(535,2809) 542,2816 542,2842 547,2847 556.92,2847 561.37,2842.55 561.37,2814.84 566.55,2809.66 579.66,2809.66 584,2814 584,2847 587,2850 598,2850 601,2847 601,2811.9 603.24,2809.66 614.66,2809.66 618,2813 618,2842.6 621.4,2846 630,2846 634,2842 634,2813.14 637.48,2809.66 684.82,2809.66 690.09,2814.93 690.09,2837.35 693.74,2841 707.41,2841 710.41,2838 710.41,2814.25 715,2809.66 739.56,2809.66 745,2804.22 745,2783.67 750.31,2778.36 765.6,2778.36 769,2781.77 769,2810.89 772.11,2814 784.97,2814 787.97,2811 787.97,2782.39 792,2778.36 807.97,2778.36 811,2781.39 811,2812.19 813.81,2815 828.76,2815 832,2811.76 832,2780.36 834,2778.36 1362.48,2778.36 1446.54,2694.3 1446.54,2643.31 1490.58,2599.27 1490.58,2588.63 1493.39,2585.81 ; 1493.21,2585.64 1515,2563.85 1515,2511 1530.07,2495.93 1543.07,2495.93 1550.23,2495.95 v2(1563.59,2482.59)
  L10-Bottom Layer w4.5: U17.5@534.52,2846.2 535,2845.72 v1(535,2809)
SFC_MOSI1: CN6.L6 U17.2 | length 1679.7
  L1-Top Layer w5.5: CN6.L6@1525.77,2495.95 v2(1538,2508.18)
  L8-SIG2 w4.5: v1(434.52,3113.48) 411.33,3113.48 407,3109.15 407,3083 414.07,3075.93 453.93,3075.93 461,3083 461,3105.52 468.96,3113.48 495.85,3113.48 537.32,3072 639.81,3072 743.81,2968 869,2968 972,2865 1349.78,2865 1553.39,2661.39 1553.39,2588.1 1576.95,2564.54 1576.95,2526.29 1572.18,2521.52 1546,2521.52 1538,2513.52 v2(1538,2508.18)
  L10-Bottom Layer w5.5: U17.2@434.52,3066.67 435,3067.15 434.52,3067.63 v1(434.52,3113.48)
SFC_MOSI2: CN6.M6 U17.3 | length 1680.8
  L1-Top Layer w5.5: CN6.M6@1525.77,2521.54 v2(1538,2533.77)
  L8-SIG2 w4.5: v1(485.5,3097.87) 485.5,3032.72 491.31,3026.92 513.58,3026.92 520.12,3033.46 520.12,3045.78 524.35,3050 544.47,3050 550,3044.47 550,3000.26 555.26,2995 570,2995 575.32,3000.32 575.32,3045.17 580.16,3050 596,3050 599,3047 599,2994 604,2989 615.08,2989 620,2993.92 620,3046 624,3050 649.08,3050 744.08,2955 864,2955 963,2856 1320.31,2856 1464.54,2711.77 1464.54,2661.87 1550.25,2576.16 1550.25,2546.02 v2(1538,2533.77)
  L10-Bottom Layer w5.5: U17.3@484.52,3066.67 485.5,3067.65 v1(485.5,3097.87)
SFC_MOSI3: CN6.N6 U17.7 | length 1677.7
  L1-Top Layer w10: CN6.N6@1525.77,2547.13 v2(1538,2559.36)
  L8-SIG2 w4.5: v1(434,2814) 434,2892 439.66,2897.66 461.96,2897.66 466,2893.62 466,2825 474,2817 490.06,2817 498.76,2825.7 498.76,2899.07 502.85,2903.16 524.36,2903.16 528,2899.52 528,2872 532.46,2867.54 547.29,2867.54 551,2871.25 551,2895.79 557.59,2902.38 584.02,2902.38 591.17,2895.23 591.17,2873.74 594.91,2870 611.17,2870 614,2872.83 614,2894.75 619,2899.75 652.69,2899.75 668.42,2884.02 730.56,2884.02 767.58,2847 1312,2847 1455.54,2703.46 1455.54,2647.04 1499.58,2603 1499.58,2592 1532.22,2559.36 v2(1538,2559.36)
  L10-Bottom Layer w5.5: v1(434,2814) 434,2845.68 U17.7@434.52,2846.2
SFC_SSN: CN6.K6 R161.1 U17.1 | length 1679.6
  L1-Top Layer w5.5: CN6.K6@1525.77,2470.36 v2(1538,2482.59)
  L8-SIG2 w4.5: v1(384.52,3098.5) 384.52,2837.48 431,2791 721.34,2791 743.98,2768.36 1285.59,2768.36 1471.95,2582 1484.08,2582 1504,2562.08 1504,2504.99 1526.39,2482.59 v2(1538,2482.59)
  L10-Bottom Layer w4.5: U17.1@384.52,3066.67 v1(384.52,3098.5) 384.52,3131.9 R161.1@386,3133.38
SI0: J11.2 U1.34 | length 934.9
  L1-Top Layer w5.5: U1.34@286.33,1126.67 327.67,1126.67 v1(328,1127)
  L3-SIG1 w4.5: v1(328,1127) 328,1263 327.83,1263.17 493.66,1429 502.66,1438 872.46,1438 968,1533.54 J11.2@968,1538.27
SI1: J11.4 U1.24 | length 669.3
  L1-Top Layer w5.5: v1(504.57,1394) U1.24@504.57,1425.31
  L3-SIG1 w4.5: v1(504.57,1394) 521.79,1411.21 966.21,1411.21 1068,1513 J11.4@1068,1538.27
SI2: J11.6 U1.23 | length 710.1
  L1-Top Layer w5.5: v1(552.62,1391.91) U1.23@552.62,1425.99
  L3-SIG1 w4.5: v1(552.62,1391.91) 1021.63,1391.91 J11.6@1168,1538.27
SN_CCLK: C28.1 CN4.34 CN6.A8 | length 1011.7
  L1-Top Layer w5.5: CN4.34@1128.58,2969.76 1152.73,2969.76 1164,2981.03 v1(1164,2990) 1164,3002.35 1169.65,3008 C28.1@1192.38,3008 ; v2@1435.64,2227.82 v2(1436.77,2227.82) 1462.36,2227.82 CN6.A8@1474.59,2240.05
  L3-SIG1 w4.5: v1(1164,2990) 1164,2938 1365.26,2736.74 1365.26,2675.97 1423.98,2617.25 1423.98,2458 1422.96,2456.98 1422.96,2300 1423.43,2299.53 1423.43,2240.03 v2@1435.64,2227.82
SN_IR_IN1: R23.1 R130.1 R138.1 R156.2 | length 4801.8
  L1-Top Layer w4: v1(735,3054) 742.38,3046.62 824.22,3046.62 848.06,3022.78 863.12,3022.78 874.19,3033.85 R23.1@874.19,3037.53
  L3-SIG1 w4: 789.76,3046.88 742.12,3046.88 v1(735,3054) 728.37,3047.37 715.51,3047.37 707,3055.88 707,3230.58 728.42,3252 900.81,3424.39 900.81,3890.81 963,3953 1052.08,3953 1060.08,3945 1060.08,3935.49 v1(1053.83,3929.24) ; 789.76,3047.03 856.04,3047.03 962.45,2940.62 962.45,2907.5 1144,2725.95 1144,2553.65 1252.88,2444.77 1296.14,2444.77 v2(1311.02,2429.89)
  L8-SIG2 w4: v2@567.65,739 570.9,742.25 570.9,755.9 616.71,801.71 791.45,801.71 872,882.26 872,2388.91 932.09,2449 1142.19,2449 1154.03,2437.16 1303.76,2437.16 v2(1311.02,2429.89)
  L10-Bottom Layer w4: R156.2@553,717.2 566.75,717.2 573.25,723.7 573.25,734 568.25,739 v2(568,739) ; R138.1@1017.6,3968.93 1017.6,3974.44 1027.37,3984.22 1053,3984.22 1061.08,3976.14 1061.08,3936.49 v1(1053.83,3929.24) ; v2(1311.02,2429.89) 1311.02,2437.55 1316.47,2443 R130.1@1333,2443 R130.1@1334.41,2443
SN_IR_IN2: R24.1 R45.1 R140.1 R155.2 | length 4777.2
  L1-Top Layer w4: v1(735,3027.74) 742.38,3035.12 819.46,3035.12 843.3,3011.28 862.72,3011.28 874.19,2999.81 R24.1@874.19,2996.53 ; v2(1277.7,2424.16) 1277.7,2407.3 R45.1@1281,2404
  L3-SIG1 w4: 789.76,3033.38 740.64,3033.38 v1(735,3027.74) 728.37,3034.37 710.12,3034.37 694,3050.49 694,3235.96 887.81,3429.78 887.81,3896.2 957.62,3966 1058.17,3966 1073.58,3950.59 1073.58,3935.49 v1(1079.83,3929.24) ; 789.76,3033.53 850.14,3033.53 949.45,2934.22 949.45,2902.11 1131,2720.56 1131,2548.27 1247.99,2431.27 1270.58,2431.27 v2(1277.7,2424.16)
  L8-SIG2 w4: v2(588.21,739) 585.07,742.14 585.07,751.68 622.09,788.71 797.27,788.71 885,876.44 885,2383.52 937.39,2435.91 1136.18,2435.91 1147.94,2424.16 v2(1277.7,2424.16)
  L10-Bottom Layer w4: v2(588.21,739) 584.75,735.54 584.75,724.25 591.08,717.92 R155.2@605,717.92 ; R140.1@1017,4011 1017,4005.56 1026.84,3995.72 1057.76,3995.72 1072.58,3980.9 1072.58,3936.49 v1(1079.83,3929.24)
SN_LDO_EN: R126.2 R144.1 | length 640.6
  L3-SIG1 w5: v2(1061,2985.27) 1076.27,2970 1104.43,2970 1332,2742.43 v2(1332,2602)
  L10-Bottom Layer w5: R126.2@1325.58,2626.58 1325.58,2608.42 v2(1332,2602)
  L10-Bottom Layer w5.5: R144.1@959.7,2985.2 1060.92,2985.2 v2(1061,2985.27)
SN_PWDN: CN6.A12 R15.1 R21.1 | length 1194.3
  L1-Top Layer w5.5: R15.1@812.62,3082 817.76,3076.86 R21.1@854.19,3076.86 854.19,3095.71 v1(866,3107.52) ; v2(1360,2227.82) CN6.A12@1372.23,2240.05
  L3-SIG1 w4.5: v1(866,3107.52) 866,3090.27 1257,2699.27 1257,2631.67 1347.09,2541.58 1347.09,2541.26 1351,2537.35 1351,2290.88 1338.29,2278.16 1338.29,2244.57 1355.04,2227.82 v2(1360,2227.82)
SN_RST#: CN4.9 CN6.A11 R20.1 | length 1267.7
  L1-Top Layer w5.5: R20.1@879.81,3138.22 884.22,3138.22 904.74,3158.74 v1(919,3158.74) CN4.9@956.35,3158.74 CN4.9@959.29,3158.74 ; v2(1385.59,2227.82) CN6.A11@1397.82,2240.05
  L3-SIG1 w4.5: v1(919,3158.74) 898.09,3137.83 898.09,3070.91 1266,2703 1266,2635.39 1359.73,2541.67 1359.73,2283.27 1346.79,2270.33 1346.79,2249.28 1356,2240.07 1365.07,2240.07 1377.32,2227.82 v2(1385.59,2227.82)
SN_SID: CN4.14 SID.1 | length 216.5
  L1-Top Layer w5.5: CN4.14@1128.58,3127.24 1153.95,3127.24 v1@1160.67,3133.96 ; v2(1182.77,3240) 1182.77,3266.4 1193.84,3277.47 SID.1@1218,3277.47
  L10-Bottom Layer w5.5: v1(1161.67,3132.96) 1182,3153.29 v2@1182,3240
SN_SIO_C: CN4.7 CN6.L13 R18.1 | length 1134.2
  L1-Top Layer w5.5: v1(879.81,3212) 875.56,3212 880,3207.56 880,3186.81 R18.1@879.44,3186.25 920.75,3186.25 932.51,3174.49 CN4.7@956.35,3174.49 CN4.7@959.29,3174.49 ; v2(1297,2502) 1297,2500.76 1299.43,2498.33 1344.26,2498.33 CN6.L13@1346.64,2495.95
  L3-SIG1 w4.5: v1(879.81,3212) 879.81,3219.19 873.02,3225.98 843.31,3225.98 836,3218.67 836,3092.53 1233.5,2695.03 1233.5,2629.71 1233.62,2629.6 1233.62,2565.34 v2@1297,2501.95
SN_SIO_D: CN4.5 CN6.L12 R19.1 | length 1131.5
  L1-Top Layer w5.5: R19.1@879.51,3239 v1(916,3239) 916,3209 934.76,3190.24 CN4.5@956.35,3190.24 CN4.5@959.29,3190.24 ; v2(1313,2512.99) 1318.16,2507.83 1360.35,2507.83 CN6.L12@1372.23,2495.95
  L3-SIG1 w4.5: v1(916,3239) 916,3207 847,3138 847,3094.25 1242.5,2698.75 1242.5,2633.44 1242.62,2633.32 1242.62,2583.37 v2(1313,2512.99)
SPI_CLK: CN6.A13 R29.2 R36.2 R58.1 | length 3287.4
  L1-Top Layer w5.5: R29.2@1037,874.93 1039.89,877.82 v1(1069,877.82) R36.2@1107.38,877.82 ; v2(1334.41,2227.82) CN6.A13@1346.64,2240.05 ; v2(1565.11,1963.13) 1567.13,1963.13 1598.84,1994.84 R58.1@1626.97,1994.84
  L10-Bottom Layer w5.5: v1(1069,877.82) 1141.82,877.82 1162.32,898.32 1179.09,898.32 1200.62,919.85 1200.62,977.65 1168.54,1009.73 1067.29,1009.73 1060.23,1016.79 1060.23,1116.23 1338.78,1394.78 1338.78,1540.78 1346.78,1548.78 1448.82,1548.78 1454,1553.96 1454,1565.54 1449.95,1569.59 1343.15,1569.59 1340,1572.74 1340,1587.24 1344.54,1591.78 1453.94,1591.78 1458,1595.83 1458,1606.48 1453.71,1610.78 1341.76,1610.78 1338.78,1613.76 1338.78,1626.78 1342.78,1630.78 1454.72,1630.78 1459.27,1635.32 1459.27,1647.86 1455.36,1651.78 1350.25,1651.78 1346,1656.03 1346,1665 1351.78,1670.78 1458,1670.78 1462,1674.78 1462,1685.98 1457.2,1690.78 1359.96,1690.78 1355.76,1694.97 1355.76,1707.52 1360.52,1712.27 1520.99,1712.27 1569,1760.29 1569,1924.41 1564.71,1928.7 1497,1928.7 1492.61,1933.09 1492.61,1948.59 1496.02,1952 1560.72,1952 1565.91,1957.19 1565.11,1957.99 v2(1565.11,1963.13) 1565.11,1967.8 1554.91,1978 1539.96,1978 1531.99,1985.97 1531.99,2001.54 1526.19,2007.34 1511.84,2007.34 1507.15,2002.65 1507.15,1986.31 1501.56,1980.73 1488.87,1980.73 1483.47,1986.12 1483.47,2003.3 1475.77,2011 1377.3,2011 1335.78,2052.52 1335.78,2226.45 v2(1334.41,2227.82)
SPI_CS: CN6.B13 R27.2 R35.2 R71.2 | length 3303.3
  L1-Top Layer w4.5: v2(1324.88,2243.88) CN6.B13@1346.64,2265.64
  L1-Top Layer w5.5: R27.2@1037,1026.34 R27.2@1040.62,1026.34 R35.2@1107.38,1026.34 ; R71.2@1972.62,308.7 v1(1972.62,333.73)
  L8-SIG2 w4.5: v1(1075.48,1025.32) 1070.47,1025.32 1022.75,977.6 1022.75,760.62 1083.37,700 1168.79,700 1280,588.79 1280,421 1411.77,289.23 1928.12,289.23 v1(1972.62,333.73)
  L10-Bottom Layer w5.5: v1(1075.48,1025.32) 1094.5,1044.35 1094.5,1127 1475,1507.5 1475,1638 1582,1745 1582,1976.7 1530.65,2028.05 1417.73,2028.05 1390.45,2055.33 1360.78,2055.33 1347.16,2068.95 1347.16,2234.29 1337.57,2243.88 v2(1324.88,2243.88)
SPI_MISO: CN6.C13 R37.2 R54.2 R121.2 | length 3300.8
  L1-Top Layer w5.5: v1(1067,925.4) R37.2@1107.38,925.4 ; v2(1322.2,2284.6) 1328.82,2291.23 CN6.C13@1346.64,2291.23 ; R54.2@1570,308 v1(1570,334.09)
  L8-SIG2 w4.5: v1(1067,925.4) 1069.4,923 1124.77,923 1130,928.23 1130,949 1123.17,955.83 1056.83,955.83 1046,945 1046,768 1087.33,726.67 1169.54,726.67 1298,598.2 1298,425 1390.35,332.65 1565.92,332.65 1567.36,334.09 v1(1570,334.09)
  L10-Bottom Layer w5.5: v1(1067,925.4) 1088.82,903.58 1141.56,903.58 1151,913.02 1151,918.56 1141.56,928 1092.63,928 1081.79,938.84 1081.79,955.83 1086.95,961 1160,961 1167.5,968.5 1167.5,985.5 1159.59,993.41 1058.52,993.41 1047.24,1004.68 1047.24,1126.24 1318,1397 1318,1707.8 1346.2,1736 1460.78,1736 1476,1751.22 1476,1891 1410.5,1956.5 1410.5,1984.63 1409.13,1986 R121.2@1405.51,1986 1384.39,1986 1325.78,2044.61 1325.78,2218.25 1314.28,2229.75 1313.94,2229.75 1311.02,2232.67 1311.02,2273.43 v2(1322.2,2284.6)
SPI_MOSI: CN6.C12 R28.2 R38.2 R59.2 | length 3297.7
  L1-Top Layer w4.5: v2(1309,2217) 1308.31,2217.69 1308.31,2246.22 1340.03,2277.94 1358.94,2277.94 CN6.C12@1372.23,2291.23
  L1-Top Layer w5.5: R28.2@1037,975.87 R28.2@1040.62,975.87 v1(1068.58,975.87) R38.2@1107.38,975.87 ; R59.2@1675,308 v1(1675,332.65)
  L8-SIG2 w4.5: v1(1068.58,975.87) 1068.8,975.64 1144.78,975.64 1162.21,958.21 1162.21,846.79 1390,619 1390,508.29 1538.29,360 1647.65,360 v1(1675,332.65)
  L10-Bottom Layer w5.5: v1(1068.58,975.87) 1047.24,954.54 1047.24,918.53 1061.81,903.96 1061.81,892.19 1055.4,885.78 1036.42,885.78 1033.2,889.01 1033.2,1136.94 1298.12,1401.87 1298.12,1433.28 1271.87,1459.53 1271.87,1480.72 1303,1511.84 1303,1537.12 1298.12,1542 1263.66,1542 1260.44,1545.22 1260.44,1562.15 1263.66,1565.38 1294.38,1565.38 1303,1574 1303,1602 1295.18,1609.82 1274.18,1609.82 1266,1618 1266,1627 1268.82,1629.82 1298.82,1629.82 1305,1636 1305,1656 1298,1663 1269,1663 1266,1666 1266,1680 1269,1683 1295,1683 1301,1689 1301,1706 1296,1711 1245,1711 1240.73,1715.27 1240.73,1728.73 1244,1732 1278,1732 1281.83,1735.83 1281.83,1751.84 1277.41,1756.26 1228.43,1756.26 1222.82,1761.87 1222.82,1776.16 1228.66,1782 1270.89,1782 1277,1788.11 1277,1801.21 1307.44,1831.65 1370.38,1831.65 1375.39,1836.66 1375.39,1978.73 1355.48,1998.64 1355.48,1998.79 1341.64,2012.62 1341.5,2012.62 1311.46,2042.67 1311.46,2214.54 v2(1309,2217)
SPKN: C2.1 CN1.1 R3.2 | length 256.4
  L1-Top Layer w4: CN1.1@127,1900 171.25,1944.25 262.25,1944.25 R3.2@297.5,1909 297.69,1908.82 C2.1@297.69,1856.07
SPKP: C1.1 CN1.2 R2.2 | length 257.3
  L1-Top Layer w4: CN1.2@127,2000 127,1998 169.25,1955.75 274.25,1955.75 R2.2@297.5,1979 297.5,2033.71 C1.1@295.38,2035.83
SW: D8.2 L1.2 TP4.1 U9.1 | length 372.1
  L1-Top Layer w20: TP4.1@1765,3762 1774.42,3762 1827.42,3709 1970,3709 2011.35,3667.65 L1.2@2011.35,3581
SYNC: CN6.D13 R26.2 R40.2 R48.2 | length 3299.5
  L1-Top Layer w4: v2(1323.17,2316.02) 1325.29,2313.9 1343.72,2313.9 CN6.D13@1346.64,2316.82
  L1-Top Layer w5.5: R26.2@1034,776 1040,782 v1(1069.43,782) 1070.43,783 R40.2@1107.38,783 ; R48.2@1377.02,311.81 1377.02,328.77 1393.92,345.66 v1(1393.92,359.07)
  L8-SIG2 w4.5: v1(1069.43,782) 1095.43,756 1170,756 1345,581 1345,407.99 v1(1393.92,359.07)
  L10-Bottom Layer w5.5: v1(1069.43,782) 1069.43,734.57 1083,721 1148.63,721 1158.54,730.91 1158.54,837.36 1147.67,848.24 1035.76,848.24 1020.57,863.43 1020.57,1151.57 1247.23,1378.23 1247.23,1421.85 1252.04,1426.66 1264.75,1426.66 1269.01,1430.92 1269.01,1441.64 1264.16,1446.49 1252.47,1446.49 1247.23,1451.73 1247.23,1594.63 1246.82,1595.04 1246.82,1606.33 1247.23,1606.74 1247.23,1678.66 1190.36,1735.53 1190.36,1813.57 1199.88,1823.1 1275.92,1823.1 1281,1828.17 1281,1842.42 1275.35,1848.08 1193.88,1848.08 1187.75,1854.21 1187.75,1867.3 1195.21,1874.77 1274.35,1874.77 1281,1881.42 1281,1893.13 1273.25,1900.88 1195.78,1900.88 1190.52,1906.13 1190.52,1920.95 1196.52,1926.94 1352.28,1926.94 1363.07,1937.73 1363.07,1976.91 1345.48,1994.5 1345.48,1994.64 1337.5,2002.62 1337.36,2002.62 1301.46,2038.53 1301.46,2186 1295.91,2191.55 1295.91,2234.49 1301.52,2240.11 1301.52,2294.38 v2(1323.17,2316.02)
SYS_ON1: C103.2 R127.1 R131.1 R135.1 SYSON1.1 U14.1 | length 2299.8
  L1-Top Layer w12: SYSON1.1@1043.87,2073.07 v1(1076.23,2073.07)
  L3-SIG1 w4.5: v1(1076.23,2073.07) 1218.3,1931 1387,1931 1442,1986 1598.13,1986 1657.13,1927 1743,1927 1769.62,1900.38 1769.62,1659.62 1689.13,1579.13 1689.13,1287.51 1406.49,1004.87 v1(1268,1004.87)
  L10-Bottom Layer w10: U14.1@1042.48,2195.21 1051.54,2195.21 1084.64,2162.11 1084.64,2082.74 v1@1076.01,2074.11
  L10-Bottom Layer w12: v1@1268,1005.23 R131.1@1297.79,1005.23 R127.1@1346.84,1005.23 1392,1005.23 C103.2@1392.79,1006.02
SYS_ON2: C104.1 R13.1 R100.1 R128.1 R129.1 R149.1 SYSON2.1 U16.1 | length 3412
  L1-Top Layer w5: v1@590.88,2526.5 R13.1@620.38,2497 ; v1(720,2941.35) 720,2976.59 SYSON2.1@720.91,2977.5
  L1-Top Layer w10: v1@590.88,2526.5 v1(590.88,2529)
  L3-SIG1 w5: v1(720,2941.35) 678.4,2899.75 607.04,2899.75 588,2880.71 588,2531.88 v1(590.88,2529) 590.88,2372.66 742.93,2220.61 930,2220.61 1055.63,2094.98 1186.54,2094.98 1277.52,2004 1624.43,2004 v1(1673.21,1955.22)
  L10-Bottom Layer w5: R149.1@721.5,2971 720,2969.5 v1(720,2941.35) U16.1@748.67,2941.35 ; R129.1@1335.17,1123 R128.1@1335.17,1165.6 ; C104.1@1383,1169.21 1379.38,1165.6 R128.1@1335.17,1165.6 ; v1(1673.21,1955.22) 1676.27,1952.17 1676.27,1676.82 1339.37,1339.93 1339.37,1169.81 R128.1@1335.17,1165.6 ; v1@1676.75,1955.22 1728.54,2007.02 1728.54,2057.24 1776.84,2105.55 1883.83,2105.55 R100.1@1903.5,2085.87
UART_RX: J13.5 R11.2 R12.2 R74.1 | length 2760.6
  L1-Top Layer w4: R12.2@494.89,623.74 494.89,618.88 487.26,611.25 487.26,592.74 506.82,573.18 488.81,555.17 488.81,549.5 494.81,543.5 687.79,543.5 699.75,531.54 699.75,498.25 706,492 J13.5@744,492 ; v2(1985.37,1965.79) 1981.64,1969.51 1981.64,1988.64 1987.84,1994.84 R74.1@2025.78,1994.84
  L3-SIG1 w4: J13.5@744,492 705.75,492 701.25,496.5 701.25,525.25 809.19,633.19 957.58,633.19 985.38,661 1199.92,661 1663.38,1124.47 1663.38,1126.52 1663.88,1127.02 1663.88,1183.59 1758,1277.71 1758,1565.49 1878,1685.49 1878,1911 1900,1933 1966.94,1933 1967.45,1933.51 1968.16,1933.51 1982.68,1948.03 1982.68,1963.1 v2(1985.37,1965.79)
UART_TX: J13.3 R6.2 R8.2 R70.1 | length 2761.7
  L1-Top Layer w4: R6.2@458.01,574.47 R6.2@460.81,574.47 ; R8.2@467.48,623.74 467.48,619.78 475.67,611.59 475.67,587.88 462.26,574.47 R6.2@460.81,574.47 ; J13.3@644,492 682.68,492 688.25,497.57 688.25,526.77 683.02,532 490.05,532 477.31,544.74 477.31,557.97 R6.2@460.81,574.47 ; R70.1@1926,1994.84 1962.98,1994.84 1970.14,1987.68 1970.14,1969.98 v2(1966.5,1966.33)
  L3-SIG1 w4: J13.3@644,492 682.25,492 688.25,498 688.25,530.63 803.81,646.19 952.19,646.19 980,674 1194.53,674 1650.38,1129.85 1650.38,1188.48 1745,1283.09 1745,1571 1865,1691 1865,1916.38 1894.62,1946 1961.56,1946 1969.18,1953.63 1969.18,1963.65 v2(1966.5,1966.33)
USB_DN: CN5.2 CN6.F1 U8.3 | length 2205.9
  L1-Top Layer w5: U8.3@1330.82,3857.82 1352.13,3857.82 ; CN5.2@1348.91,3981.38 1348.91,3959.05 1355.95,3952 1355.95,3860.56 ; CN6.F1@1653.72,2368 1659.46,2362.26 1919.48,2362.26 1939,2381.78 1939,2598.05 1802.17,2734.88 1739.24,2734.88 1575,2899.11 1575,3193.41 1355.95,3412.46 1355.95,3855 ; 1355.95,3855 1355.95,3860.56 ; 1355.95,3855 1353.13,3857.82 1353.21,3857.82 1355.95,3860.56
USB_DP: CN5.3 CN6.E1 U8.5 | length 2227.7
  L1-Top Layer w5: CN5.3@1374.5,3981.38 1374.5,3960.29 1367.45,3953.25 1367.45,3900.54 ; U8.5@1389.09,3897.19 1370.8,3897.19 ; CN6.E1@1653.72,2342.41 1653.72,2347.83 1656.66,2350.76 1924.24,2350.76 1950.5,2377.02 1950.5,2602.81 1806.93,2746.38 1744,2746.38 1586.5,2903.88 1586.5,3198.17 1367.45,3417.22 1367.45,3893.84 ; 1367.45,3893.84 1370.8,3897.19 ; 1367.45,3893.84 1367.45,3900.54 ; 1367.45,3900.54 1370.8,3897.19
V1P1: FB7.1 J14.1 | length 99.1
  L10-Bottom Layer w10: v2(1193.4,2015.28) 1201.91,2006.77 1229.43,2006.77 1229.51,2006.69 1229.51,2014.95 1229.51,2035.08 1219.86,2044.74 v2(1202.44,2044.74)
V1P1_OV: C35.1 C36.1 C77.2 C81.2 C85.2 C86.2 C88.2 C91.2 C92.2 C94.2 C96.2 C97.2 C98.2 C105.2 CN6.D6 CN6.D7 CN6.D8 CN6.F9 CN6.G3 CN6.G5 CN6.G9 CN6.H4 CN6.H6 CN6.H7 CN6.H8 CN6.J6 CN6.J7 CN6.K4 CN6.M13 FB7.2 OV_1.1V.1 | length 1277.3
  L1-Top Layer w8: v2(1436.2,2380.8) CN6.F9@1449,2368
  L1-Top Layer w10: OV_1.1V.1@1058.49,2224.44 v1@1120.82,2224.44 ; v2(1315.2,2532) 1327.62,2519.58 1344.68,2519.58 CN6.M13@1346.64,2521.54 ; v2@1361.93,2041.22 1361.93,2068.23 1355,2075.16 C36.1@1360.11,2075.16 1360.11,2074.82 1388.25,2046.68 v2(1388.25,2038.27) ; v2@1436.2,2406.39 CN6.G9@1449,2393.59 ; v2(1462.36,2431.41) CN6.H8@1474.59,2419.18 ; CN6.D8@1474.59,2316.82 v2(1486.82,2304.59) ; v2(1487.95,2431.41) CN6.H7@1500.18,2419.18 ; v2(1487.95,2457) CN6.J7@1500.18,2444.77 ; CN6.D7@1500.18,2316.82 v2@1512.41,2329.05 ; v2(1513.54,2329.05) CN6.D6@1525.77,2316.82 ; CN6.H6@1525.77,2419.18 v2(1538,2431.41) ; CN6.J6@1525.77,2444.77 v2(1538,2457) ; CN6.G5@1551.36,2393.59 v2(1563.59,2381.36) ; CN6.H4@1576.95,2419.18 1588.73,2407.4 CN6.G3@1602.54,2393.59 ; CN6.K4@1576.95,2470.36 v2(1589.18,2482.59)
  L3-SIG1 w10: v1(1122.49,2224.44) 1157.68,2224.44 1340.9,2041.22 v2@1361.93,2041.22 ; v2(1538,2431.41) v2(1538,2457)
  L10-Bottom Layer w4: v2(1435.21,2406.39) 1435.21,2397.77 1447.96,2385.02 1447.96,2374.05 C94.2@1462.01,2360
  L10-Bottom Layer w5: C94.2@1460.51,2358.5 C94.2@1462.01,2357 ; v2(1589.18,2482.59) 1602.34,2495.75 1609.52,2495.75 1609.59,2495.68 1619.95,2495.68 1620.02,2495.75 1626.3,2495.75 1666.05,2456 C77.2@1675,2456
  L10-Bottom Layer w8: C88.2@1519.01,2357 1519.01,2334.51 v2(1513.54,2329.05) 1526.01,2316.58 C86.2@1526.01,2303
  L10-Bottom Layer w10: v2(1315.2,2532) 1315.2,2549.61 1324.96,2559.36 C105.2@1347.01,2559.36 ; C98.2@1458.99,2326 C98.2@1458.99,2327 1458.99,2353.98 C94.2@1462.01,2357 ; v2(1462.36,2431.41) 1466.08,2431.41 1480.99,2416.5 C97.2@1480.99,2406 ; C96.2@1482,2283.14 1482,2299.77 v2(1486.82,2304.59) ; v2(1487.95,2431.41) 1499.58,2431.41 C92.2@1512,2418.99 ; C91.2@1513,2463.01 1531.99,2463.01 v2(1538,2457) ; v2(1563.59,2381.36) 1568.99,2386.76 C85.2@1568.99,2405 ; v2@1588.73,2407.4 1624.41,2407.4 C81.2@1631.01,2414
  other v2: 1316.47,1983.29 1331.86,1989 1367.23,2041 1588.73,2406.39
V1P8: C40.1 CN9.4 FB4.1 FB10.1 J12.1 R105.2 | length 239.7
  L1-Top Layer w8: FB4.1@1368.24,3039.33 1374.91,3046 1407.13,3046 1409.18,3048.06 1410.41,3048.06 C40.1@1410.41,3049.84
  L1-Top Layer w10: C40.1@1410.41,3048.06 1409.9,3047.54 1409.9,3047.28 1411.93,3045.25 1432.18,3025 v1(1436,3025) ; C40.1@1410.41,3049.84 1410.58,3050 v1(1435.68,3050)
  L10-Bottom Layer w8: v2(1183.24,2281.3) 1183.24,2268.27 FB10.1@1193.81,2257.7 1202,2265.89 v2@1202,2282.43
  L10-Bottom Layer w10: v1(1768.36,2047) 1774.07,2047 1800.38,2073.31 1796.69,2077 v1(1770.45,2077)
  other v2: 1202.22,2282.65
V1P8_OV: C47.2 C74.2 C76.2 C90.2 C99.2 C106.2 C128.1 CN6.B2 CN6.C9 CN6.C11 CN6.L2 CN6.L8 FB10.2 OV_1.8V.1 R55.2 R56.2 R57.2 R111.2 R117.2 R122.2 R161.2 U17.8 VCC_MEM.1 | length 979.4
  L1-Top Layer w5: CN6.B2@1628.13,2265.64 1639.65,2277.16 1666.83,2277.16 1680.35,2263.64 C47.2@1725.84,2263.64
  L1-Top Layer w8: VCC_MEM.1@1572.29,1446.12 1580.17,1454 v2(1607.24,1454)
  L1-Top Layer w10: OV_1.8V.1@1246.25,2208.13 1275,2236.89 v2(1275,2246.29) ; v2(1385.59,2279) CN6.C11@1397.82,2291.23 ; v2(1436.77,2279) CN6.C9@1449,2291.23 ; v2(1462.36,2508.18) CN6.L8@1474.59,2495.95 ; v2(1573.64,1406.03) 1578.54,1401.12 R57.2@1635.67,1401.12 ; v2(1594.69,1382) 1594.69,1379.7 1616.26,1358.12 R56.2@1635.48,1358.12 ; v2(1607.24,1454) 1615.12,1446.12 R55.2@1635.48,1446.12 ; CN6.L2@1628.13,2495.95 v2(1640.36,2508.18) ; C47.2@1725.84,2263.64 1726,2263.8 v2(1726,2286)
  L10-Bottom Layer w4: v2(1462.36,2508.18) 1475.18,2521 1492.15,2521 ; 1492.16,2521.01 1509.65,2521.01 C90.2@1513.15,2524.51
  L10-Bottom Layer w6: v2(1640.36,2508.18) 1655.18,2523 1696.01,2523 C76.2@1702,2517.01
  L10-Bottom Layer w10: U17.8@384.52,2846.2 C128.1@384.52,2780.5 383.03,2779 384.31,2777.71 v1(417,2777.71) ; R161.2@384.52,3189.07 R161.2@385.59,3188 ; v1(385.59,3216.41) R161.2@385.59,3188 ; v1(414,3188) R161.2@385.59,3188 ; FB10.2@1246.96,2257.7 1255.96,2266.7 v2(1275.22,2266.7) ; C106.2@1367.72,2298.62 1385.59,2280.76 v2(1385.59,2279) ; v2(1436.77,2279) 1446.99,2289.22 C99.2@1446.99,2296 ; v2@1441,2054.76 R122.2@1441,2097.2 ; v2(1561.72,2068.4) 1535,2095.12 R117.2@1535,2097.67 1564.95,2097.67 1568.62,2094 R111.2@1600.38,2094 ; v2(1726,2286) 1739,2299 C74.2@1746.02,2299
  other v2: 1442.24,2054.76 1565.06,2097.79
V1P8_SN_DVDD: C29.1 C37.1 CN4.36 CN4.38 DVDD.1 FB4.2 R15.2 R18.2 R19.2 R20.2 | length 612.1
  L1-Top Layer w8: R15.2@765.38,3082 v1(765.38,3111.5) ; CN4.38@1125.65,2938.27 1149.92,2938.27 1155.82,2944.16 1155.82,2954.02 ; CN4.36@1125.65,2954.02 1151.69,2954.02 ; 1154.47,2951.23 1151.69,2954.02 ; v1(1405,2968) 1384.24,2968 1368.24,2984 FB4.2@1368.24,2986.18 ; v1(1405,2990) 1372.91,2990 1372.48,2990.43 FB4.2@1368.24,2986.18 ; 1151.69,2954.02 1155.82,2954.02 ; 1155.82,2954.02 1166.51,2964.71 C29.1@1188.79,2964.71 1208.09,2984 1300.86,2984 1304.75,2980.12 1362.17,2980.12 FB4.2@1368.24,2986.18
  L1-Top Layer w10: v1@800.81,3186.25 R18.2@832.19,3186.25 ; v1@800.88,3239 R19.2@832.26,3239 832.26,3270.18 807.88,3294.56 DVDD.1@807.88,3327.59 ; v1@801.19,3138.22 R20.2@832.57,3138.22
  other v1: 801.19,3138.51 800.81,3186.53 800.88,3239.29
V1P35: FB5.1 J6.1 | length 58.2
  L1-Top Layer w8: v2@1672,2046.4 FB5.1@1672,2079.5 v2@1697.14,2079.5
  other v2: 1671.52,2045.91 1697.5,2079.14
V1P35_OV: C42.1 C44.1 C51.2 C78.2 C80.2 C84.2 CN6.C2 CN6.C3 CN6.C4 CN6.D3 CN6.D4 CN6.E4 CN6.E5 FB5.2 OV_1.35V.1 R104.2 | length 529.4
  L1-Top Layer w8: v2(1563.59,2330.18) CN6.D4@1576.95,2316.82 ; v2(1616.17,2279.26) CN6.C2@1628.13,2291.23 ; C51.2@1866.05,2296.35 1866.05,2308.71 v2(1871.68,2314.34) ; C51.2@1866.24,2291.5 1879.76,2291.5 1889.67,2301.41 v2(1889.67,2312.04) 1969.65,2312.04 2025.03,2367.42 OV_1.35V.1@2051,2367.42
  L1-Top Layer w10: CN6.E5@1551.36,2342.41 v2(1563.59,2330.18) ; CN6.C4@1576.95,2291.23 v2(1586.59,2281.59) ; CN6.E4@1576.95,2342.41 v2(1589.18,2330.18) ; CN6.C3@1602.54,2291.23 1614.51,2279.26 v2(1616.17,2279.26) ; CN6.D3@1602.54,2316.82 v2(1614.77,2304.59)
  L10-Bottom Layer w5: C84.2@1570.01,2236 1573.5,2239.49 1573.5,2268.5 v2(1586.59,2281.59)
  L10-Bottom Layer w8: v2@1587.98,2328.98 v2(1589.18,2330.18) ; v2(1614.77,2304.59) 1617.34,2304.59 1634.75,2322 C78.2@1642,2322 ; v2(1871.68,2314.34) 1871.68,2306.32 1885.66,2292.34 R104.2@1887.62,2292.34 1889.67,2294.39 v2(1889.67,2312.04)
  L10-Bottom Layer w10: v2(1616.17,2279.26) 1632.01,2263.43 C80.2@1632.01,2258
  other v2: 1669.68,2157.59 1688,2158.22 1597.04,2172.7 1614.24,2172.7 1631,2172.7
